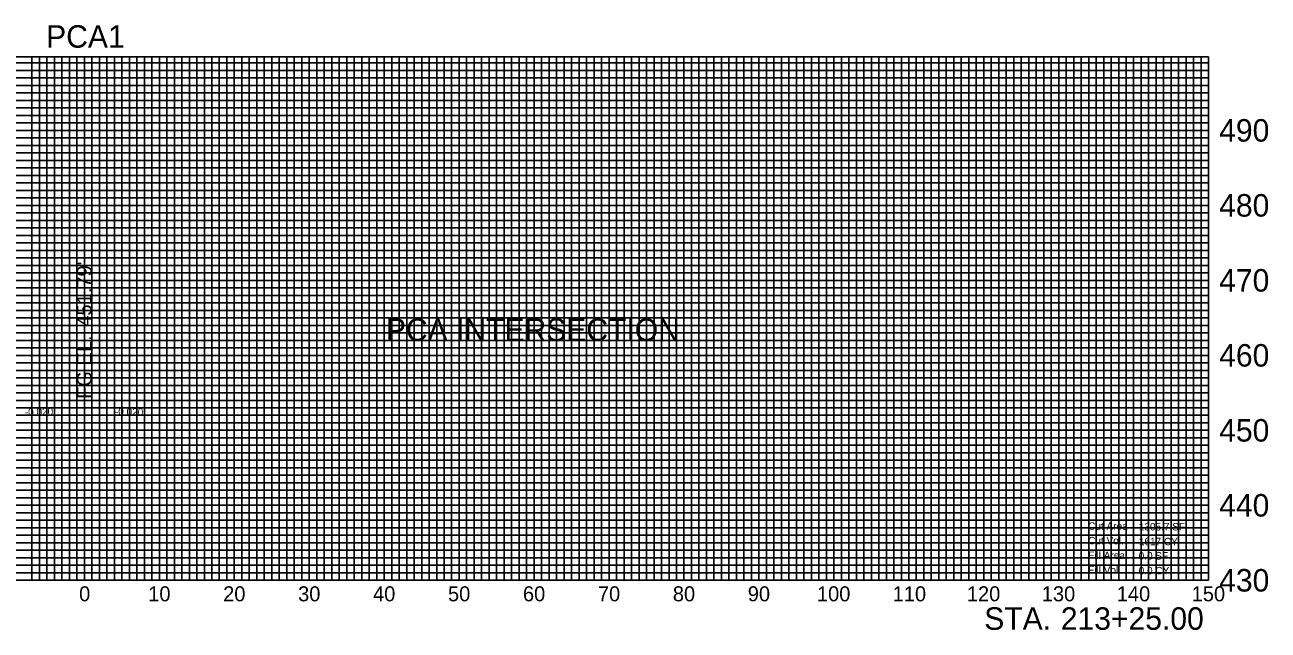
# Model space of a CAD drawing. Extents: x -158 to 158, y 423 to 504.
# Drawn here: x -7.9 to 157.9, y 423.4 to 504.1 of the extents above; entities that cross this region are included whole.
import ezdxf

# ---------------------------------------------------------------- set-up
doc = ezdxf.new("R2010")
doc.units = 0
for name, color, linetype in [('Default', 7, 'Continuous'), ('DES - SHEET - Light Grid', 7, 'Continuous'), ('DES - SHEET - Linework', 7, 'Continuous'), ('DES - XS - Earthwork - Cut Text', 7, 'Continuous'), ('DES - XS - Earthwork - Fill Text', 7, 'Continuous'), ('DES - XS - Proposed - Finished Grade Slopes Text', 7, 'Continuous'), ('DES - XS - Proposed - Text', 7, 'Continuous'), ('Draft_XS_Volume_Annotation', 7, 'Continuous')]:
    doc.layers.add(name, color=color, linetype=linetype)

msp = doc.modelspace()

# ---------------------------------------------------------------- linework, layer by layer
at = {"layer": 'Default'}
msp.add_circle((0, 438.4), 0.012, dxfattribs=at)
msp.add_circle((0, 438.4), 0.012, dxfattribs=at)
msp.add_circle((0, 438.4), 0.012, dxfattribs=at)
at = {"layer": 'DES - SHEET - Light Grid'}
for p, q in [((-7, 430), (-7, 499.82)), ((-7, 430), (-7, 499.82)), ((-6, 430), (-6, 499.82)), ((-6, 430), (-6, 499.82)), ((-5, 430), (-5, 499.82)), ((-5, 430), (-5, 499.82)), ((-4, 430), (-4, 499.82)), ((-4, 430), (-4, 499.82)), ((-3, 430), (-3, 499.82)), ((-3, 430), (-3, 499.82)), ((-2, 430), (-2, 499.82)), ((-2, 430), (-2, 499.82)), ((-1, 430), (-1, 499.82)), ((-1, 430), (-1, 499.82)), ((1, 430), (1, 499.82)), ((1, 430), (1, 499.82)), ((2, 430), (2, 499.82)), ((2, 430), (2, 499.82)), ((3, 430), (3, 499.82)), ((3, 430), (3, 499.82)), ((4, 430), (4, 499.82)), ((4, 430), (4, 499.82)), ((5, 430), (5, 499.82)), ((5, 430), (5, 499.82)), ((6, 430), (6, 499.82)), ((6, 430), (6, 499.82)), ((7, 430), (7, 499.82)), ((7, 430), (7, 499.82)), ((8, 430), (8, 499.82)), ((8, 430), (8, 499.82)), ((9, 430), (9, 499.82)), ((9, 430), (9, 499.82)), ((11, 430), (11, 499.82)), ((11, 430), (11, 499.82)), ((12, 430), (12, 499.82)), ((12, 430), (12, 499.82)), ((13, 430), (13, 499.82)), ((13, 430), (13, 499.82)), ((14, 430), (14, 499.82)), ((14, 430), (14, 499.82)), ((15, 430), (15, 499.82)), ((15, 430), (15, 499.82)), ((16, 430), (16, 499.82)), ((16, 430), (16, 499.82)), ((17, 430), (17, 499.82)), ((17, 430), (17, 499.82)), ((18, 430), (18, 499.82)), ((18, 430), (18, 499.82)), ((19, 430), (19, 499.82)), ((19, 430), (19, 499.82)), ((21, 430), (21, 499.82)), ((21, 430), (21, 499.82)), ((22, 430), (22, 499.82)), ((22, 430), (22, 499.82)), ((23, 430), (23, 499.82)), ((23, 430), (23, 499.82)), ((24, 430), (24, 499.82)), ((24, 430), (24, 499.82)), ((25, 430), (25, 499.82)), ((25, 430), (25, 499.82)), ((26, 430), (26, 499.82)), ((26, 430), (26, 499.82)), ((27, 430), (27, 499.82)), ((27, 430), (27, 499.82)), ((28, 430), (28, 499.82)), ((28, 430), (28, 499.82)), ((29, 430), (29, 499.82)), ((29, 430), (29, 499.82)), ((31, 430), (31, 499.82)), ((31, 430), (31, 499.82)), ((32, 430), (32, 499.82)), ((32, 430), (32, 499.82)), ((33, 430), (33, 499.82)), ((33, 430), (33, 499.82)), ((34, 430), (34, 499.82)), ((34, 430), (34, 499.82)), ((35, 430), (35, 499.82)), ((35, 430), (35, 499.82)), ((36, 430), (36, 499.82)), ((36, 430), (36, 499.82)), ((37, 430), (37, 499.82)), ((37, 430), (37, 499.82)), ((38, 430), (38, 499.82)), ((38, 430), (38, 499.82)), ((39, 430), (39, 499.82)), ((39, 430), (39, 499.82)), ((41, 430), (41, 499.82)), ((41, 430), (41, 499.82)), ((42, 430), (42, 499.82)), ((42, 430), (42, 499.82)), ((43, 430), (43, 499.82)), ((43, 430), (43, 499.82)), ((44, 430), (44, 499.82)), ((44, 430), (44, 499.82)), ((45, 430), (45, 499.82)), ((45, 430), (45, 499.82)), ((46, 430), (46, 499.82)), ((46, 430), (46, 499.82)), ((47, 430), (47, 499.82)), ((47, 430), (47, 499.82)), ((48, 430), (48, 499.82)), ((48, 430), (48, 499.82)), ((49, 430), (49, 499.82)), ((49, 430), (49, 499.82)), ((51, 430), (51, 499.82)), ((51, 430), (51, 499.82)), ((52, 430), (52, 499.82)), ((52, 430), (52, 499.82)), ((53, 430), (53, 499.82)), ((53, 430), (53, 499.82)), ((54, 430), (54, 499.82)), ((54, 430), (54, 499.82)), ((55, 430), (55, 499.82)), ((55, 430), (55, 499.82)), ((56, 430), (56, 499.82)), ((56, 430), (56, 499.82)), ((57, 430), (57, 499.82)), ((57, 430), (57, 499.82)), ((58, 430), (58, 499.82)), ((58, 430), (58, 499.82)), ((59, 430), (59, 499.82)), ((59, 430), (59, 499.82)), ((61, 430), (61, 499.82)), ((61, 430), (61, 499.82)), ((62, 430), (62, 499.82)), ((62, 430), (62, 499.82)), ((63, 430), (63, 499.82)), ((63, 430), (63, 499.82)), ((64, 430), (64, 499.82)), ((64, 430), (64, 499.82)), ((65, 430), (65, 499.82)), ((65, 430), (65, 499.82)), ((66, 430), (66, 499.82)), ((66, 430), (66, 499.82)), ((67, 430), (67, 499.82)), ((67, 430), (67, 499.82)), ((68, 430), (68, 499.82)), ((68, 430), (68, 499.82)), ((69, 430), (69, 499.82)), ((69, 430), (69, 499.82)), ((71, 430), (71, 499.82)), ((71, 430), (71, 499.82)), ((72, 430), (72, 499.82)), ((72, 430), (72, 499.82)), ((73, 430), (73, 499.82)), ((73, 430), (73, 499.82)), ((74, 430), (74, 499.82)), ((74, 430), (74, 499.82)), ((75, 430), (75, 499.82)), ((75, 430), (75, 499.82)), ((76, 430), (76, 499.82)), ((76, 430), (76, 499.82)), ((77, 430), (77, 499.82)), ((77, 430), (77, 499.82)), ((78, 430), (78, 499.82)), ((78, 430), (78, 499.82)), ((79, 430), (79, 499.82)), ((79, 430), (79, 499.82)), ((81, 430), (81, 499.82)), ((81, 430), (81, 499.82)), ((82, 430), (82, 499.82)), ((82, 430), (82, 499.82)), ((83, 430), (83, 499.82)), ((83, 430), (83, 499.82)), ((84, 430), (84, 499.82)), ((84, 430), (84, 499.82)), ((85, 430), (85, 499.82)), ((85, 430), (85, 499.82)), ((86, 430), (86, 499.82)), ((86, 430), (86, 499.82)), ((87, 430), (87, 499.82)), ((87, 430), (87, 499.82)), ((88, 430), (88, 499.82)), ((88, 430), (88, 499.82)), ((89, 430), (89, 499.82)), ((89, 430), (89, 499.82)), ((91, 430), (91, 499.82)), ((91, 430), (91, 499.82)), ((92, 430), (92, 499.82)), ((92, 430), (92, 499.82)), ((93, 430), (93, 499.82)), ((93, 430), (93, 499.82)), ((94, 430), (94, 499.82)), ((94, 430), (94, 499.82)), ((95, 430), (95, 499.82)), ((95, 430), (95, 499.82)), ((96, 430), (96, 499.82)), ((96, 430), (96, 499.82)), ((97, 430), (97, 499.82)), ((97, 430), (97, 499.82)), ((98, 430), (98, 499.82)), ((98, 430), (98, 499.82)), ((99, 430), (99, 499.82)), ((99, 430), (99, 499.82)), ((101, 430), (101, 499.82)), ((101, 430), (101, 499.82)), ((102, 430), (102, 499.82)), ((102, 430), (102, 499.82)), ((103, 430), (103, 499.82)), ((103, 430), (103, 499.82)), ((104, 430), (104, 499.82)), ((104, 430), (104, 499.82)), ((105, 430), (105, 499.82)), ((105, 430), (105, 499.82)), ((106, 430), (106, 499.82)), ((106, 430), (106, 499.82)), ((107, 430), (107, 499.82)), ((107, 430), (107, 499.82)), ((108, 430), (108, 499.82)), ((108, 430), (108, 499.82)), ((109, 430), (109, 499.82)), ((109, 430), (109, 499.82)), ((111, 430), (111, 499.82)), ((111, 430), (111, 499.82)), ((112, 430), (112, 499.82)), ((112, 430), (112, 499.82)), ((113, 430), (113, 499.82)), ((113, 430), (113, 499.82)), ((114, 430), (114, 499.82)), ((114, 430), (114, 499.82)), ((115, 430), (115, 499.82)), ((115, 430), (115, 499.82)), ((116, 430), (116, 499.82)), ((116, 430), (116, 499.82)), ((117, 430), (117, 499.82)), ((117, 430), (117, 499.82)), ((118, 430), (118, 499.82)), ((118, 430), (118, 499.82)), ((119, 430), (119, 499.82)), ((119, 430), (119, 499.82)), ((121, 430), (121, 499.82)), ((121, 430), (121, 499.82)), ((122, 430), (122, 499.82)), ((122, 430), (122, 499.82)), ((123, 430), (123, 499.82)), ((123, 430), (123, 499.82)), ((124, 430), (124, 499.82)), ((124, 430), (124, 499.82)), ((125, 430), (125, 499.82)), ((125, 430), (125, 499.82)), ((126, 430), (126, 499.82)), ((126, 430), (126, 499.82)), ((127, 430), (127, 499.82)), ((127, 430), (127, 499.82)), ((128, 430), (128, 499.82)), ((128, 430), (128, 499.82)), ((129, 430), (129, 499.82)), ((129, 430), (129, 499.82)), ((131, 430), (131, 499.82)), ((131, 430), (131, 499.82)), ((132, 430), (132, 499.82)), ((132, 430), (132, 499.82)), ((133, 430), (133, 499.82)), ((133, 430), (133, 499.82)), ((134, 430), (134, 499.82)), ((134, 430), (134, 499.82)), ((135, 430), (135, 499.82)), ((135, 430), (135, 499.82)), ((136, 430), (136, 499.82)), ((136, 430), (136, 499.82)), ((137, 430), (137, 499.82)), ((137, 430), (137, 499.82)), ((138, 430), (138, 499.82)), ((138, 430), (138, 499.82)), ((139, 430), (139, 499.82)), ((139, 430), (139, 499.82)), ((141, 430), (141, 499.82)), ((141, 430), (141, 499.82)), ((142, 430), (142, 499.82)), ((142, 430), (142, 499.82)), ((143, 430), (143, 499.82)), ((143, 430), (143, 499.82)), ((144, 430), (144, 499.82)), ((144, 430), (144, 499.82)), ((145, 430), (145, 499.82)), ((145, 430), (145, 499.82)), ((146, 430), (146, 499.82)), ((146, 430), (146, 499.82)), ((147, 430), (147, 499.82)), ((147, 430), (147, 499.82)), ((148, 430), (148, 499.82)), ((148, 430), (148, 499.82)), ((149, 430), (149, 499.82)), ((149, 430), (149, 499.82)), ((-150, 499), (150, 499)), ((-150, 499), (150, 499)), ((-150, 498), (150, 498)), ((-150, 498), (150, 498)), ((-150, 497), (150, 497)), ((-150, 497), (150, 497)), ((-150, 496), (150, 496)), ((-150, 496), (150, 496)), ((-150, 495), (150, 495)), ((-150, 495), (150, 495)), ((-150, 494), (150, 494)), ((-150, 494), (150, 494)), ((-150, 493), (150, 493)), ((-150, 493), (150, 493)), ((-150, 492), (150, 492)), ((-150, 492), (150, 492)), ((-150, 491), (150, 491)), ((-150, 491), (150, 491)), ((-150, 489), (150, 489)), ((-150, 489), (150, 489)), ((-150, 488), (150, 488)), ((-150, 488), (150, 488)), ((-150, 487), (150, 487)), ((-150, 487), (150, 487)), ((-150, 486), (150, 486)), ((-150, 486), (150, 486)), ((-150, 485), (150, 485)), ((-150, 485), (150, 485)), ((-150, 484), (150, 484)), ((-150, 484), (150, 484)), ((-150, 483), (150, 483)), ((-150, 483), (150, 483)), ((-150, 482), (150, 482)), ((-150, 482), (150, 482)), ((-150, 481), (150, 481)), ((-150, 481), (150, 481)), ((-150, 479), (150, 479)), ((-150, 479), (150, 479)), ((-150, 478), (150, 478)), ((-150, 478), (150, 478)), ((-150, 477), (150, 477)), ((-150, 477), (150, 477)), ((-150, 476), (150, 476)), ((-150, 476), (150, 476)), ((-150, 475), (150, 475)), ((-150, 475), (150, 475)), ((-150, 474), (150, 474)), ((-150, 474), (150, 474)), ((-150, 473), (150, 473)), ((-150, 473), (150, 473)), ((-150, 472), (150, 472)), ((-150, 472), (150, 472)), ((-150, 471), (150, 471)), ((-150, 471), (150, 471)), ((-150, 469), (150, 469)), ((-150, 469), (150, 469)), ((-150, 468), (150, 468)), ((-150, 468), (150, 468)), ((-150, 467), (150, 467)), ((-150, 467), (150, 467)), ((-150, 466), (150, 466)), ((-150, 466), (150, 466)), ((-150, 465), (150, 465)), ((-150, 465), (150, 465)), ((-150, 464), (150, 464)), ((-150, 464), (150, 464)), ((-150, 463), (150, 463)), ((-150, 463), (150, 463)), ((-150, 462), (150, 462)), ((-150, 462), (150, 462)), ((-150, 461), (150, 461)), ((-150, 461), (150, 461)), ((-150, 459), (150, 459)), ((-150, 459), (150, 459)), ((-150, 458), (150, 458)), ((-150, 458), (150, 458)), ((-150, 457), (150, 457)), ((-150, 457), (150, 457)), ((-150, 456), (150, 456)), ((-150, 456), (150, 456)), ((-150, 455), (150, 455)), ((-150, 455), (150, 455)), ((-150, 454), (150, 454)), ((-150, 454), (150, 454)), ((-150, 453), (150, 453)), ((-150, 453), (150, 453)), ((-150, 452), (150, 452)), ((-150, 452), (150, 452)), ((-150, 451), (150, 451)), ((-150, 451), (150, 451)), ((-150, 449), (150, 449)), ((-150, 449), (150, 449)), ((-150, 448), (150, 448)), ((-150, 448), (150, 448)), ((-150, 447), (150, 447)), ((-150, 447), (150, 447)), ((-150, 446), (150, 446)), ((-150, 446), (150, 446)), ((-150, 445), (150, 445)), ((-150, 445), (150, 445)), ((-150, 444), (150, 444)), ((-150, 444), (150, 444)), ((-150, 443), (150, 443)), ((-150, 443), (150, 443)), ((-150, 442), (150, 442)), ((-150, 442), (150, 442)), ((-150, 441), (150, 441)), ((-150, 441), (150, 441)), ((-150, 439), (150, 439)), ((-150, 439), (150, 439)), ((-150, 438), (150, 438)), ((-150, 438), (150, 438)), ((-150, 437), (150, 437)), ((-150, 437), (150, 437)), ((-150, 436), (150, 436)), ((-150, 436), (150, 436)), ((-150, 435), (150, 435)), ((-150, 435), (150, 435)), ((-150, 434), (150, 434)), ((-150, 434), (150, 434)), ((-150, 433), (150, 433)), ((-150, 433), (150, 433)), ((-150, 432), (150, 432)), ((-150, 432), (150, 432)), ((-150, 431), (150, 431)), ((-150, 431), (150, 431))]:
    msp.add_line(p, q, dxfattribs=at)
at = {"layer": 'DES - SHEET - Linework'}
for p, q in [((-150, 499.82), (150, 499.82)), ((-150, 499.82), (150, 499.82)), ((0, 430), (0, 499.82)), ((0, 430), (0, 499.82)), ((10, 430), (10, 499.82)), ((10, 430), (10, 499.82)), ((20, 430), (20, 499.82)), ((20, 430), (20, 499.82)), ((30, 430), (30, 499.82)), ((30, 430), (30, 499.82)), ((40, 430), (40, 499.82)), ((40, 430), (40, 499.82)), ((50, 430), (50, 499.82)), ((50, 430), (50, 499.82)), ((60, 430), (60, 499.82)), ((60, 430), (60, 499.82)), ((70, 430), (70, 499.82)), ((70, 430), (70, 499.82)), ((80, 430), (80, 499.82)), ((80, 430), (80, 499.82)), ((90, 430), (90, 499.82)), ((90, 430), (90, 499.82)), ((100, 430), (100, 499.82)), ((100, 430), (100, 499.82)), ((110, 430), (110, 499.82)), ((110, 430), (110, 499.82)), ((120, 430), (120, 499.82)), ((120, 430), (120, 499.82)), ((130, 430), (130, 499.82)), ((130, 430), (130, 499.82)), ((140, 430), (140, 499.82)), ((140, 430), (140, 499.82)), ((150, 430), (150, 499.82)), ((150, 430), (150, 499.82)), ((-150, 490), (150, 490)), ((-150, 490), (150, 490)), ((-150, 480), (150, 480)), ((-150, 480), (150, 480)), ((-150, 470), (150, 470)), ((-150, 470), (150, 470)), ((-150, 460), (150, 460)), ((-150, 460), (150, 460)), ((-150, 450), (150, 450)), ((-150, 450), (150, 450)), ((-150, 440), (150, 440)), ((-150, 440), (150, 440)), ((-150, 430), (150, 430)), ((-150, 430), (150, 430))]:
    msp.add_line(p, q, dxfattribs=at)
at = {"layer": 'Draft_XS_Volume_Annotation'}
msp.add_circle((0, 438.4), 0.012, dxfattribs=at)
msp.add_circle((0, 438.4), 0.012, dxfattribs=at)
msp.add_circle((0, 438.4), 0.012, dxfattribs=at)
msp.add_circle((0, 438.4), 0.012, dxfattribs=at)
msp.add_circle((0, 438.4), 0.012, dxfattribs=at)
msp.add_circle((0, 438.4), 0.012, dxfattribs=at)

# ---------------------------------------------------------------- texts
at = {"layer": 'DES - XS - Earthwork - Cut Text'}
for s, p in [('Cut Area', (133.93, 436.74)), ('1305.7 SF', (140.69, 436.65)), ('Cut Vol.', (133.93, 434.79)), ('1617 CY', (140.69, 434.67))]:
    msp.add_text(s, height=1, dxfattribs=at).set_placement(p)
at = {"layer": 'DES - XS - Earthwork - Fill Text'}
for s, p in [('Fill Area', (133.93, 432.83)), ('0.0 SF', (140.67, 432.76)), ('Fill Vol.', (133.93, 430.88)), ('0.0 CY', (140.67, 430.79))]:
    msp.add_text(s, height=1, dxfattribs=at).set_placement(p)
at = {"layer": 'DES - XS - Proposed - Finished Grade Slopes Text'}
for rotation, p in [(1.1458, (-7.95, 451.93)), (1.1458, (-7.95, 451.93)), (358.8542, (4.05, 452.01)), (358.8542, (4.05, 452.01))]:
    msp.add_text('-0.020', height=1, rotation=rotation, dxfattribs=at).set_placement(p)
at = {"layer": 'DES - XS - Proposed - Text'}
for s, height, p in [('PCA1', 3, (-5.11, 501.02)), ('PCA1', 3, (-5.11, 501.02)), ('490', 3, (151.41, 488.5)), ('490', 3, (151.41, 488.5)), ('480', 3, (151.41, 478.5)), ('480', 3, (151.41, 478.5)), ('470', 3, (151.41, 468.5)), ('470', 3, (151.41, 468.5)), ('PCA INTERSECTION', 3, (40.22, 461.91)), ('460', 3, (151.41, 458.5)), ('460', 3, (151.41, 458.5)), ('450', 3, (151.41, 448.5)), ('450', 3, (151.41, 448.5)), ('440', 3, (151.41, 438.5)), ('440', 3, (151.41, 438.5)), ('430', 3, (151.41, 428.5)), ('430', 3, (151.41, 428.5)), ('0', 2, (-0.71, 427.2)), ('0', 2, (-0.71, 427.2)), ('10', 2, (8.51, 427.2)), ('10', 2, (8.51, 427.2)), ('20', 2, (18.51, 427.2)), ('20', 2, (18.51, 427.2)), ('30', 2, (28.51, 427.2)), ('30', 2, (28.51, 427.2)), ('40', 2, (38.51, 427.2)), ('40', 2, (38.51, 427.2)), ('50', 2, (48.51, 427.2)), ('50', 2, (48.51, 427.2)), ('60', 2, (58.51, 427.2)), ('60', 2, (58.51, 427.2)), ('70', 2, (68.51, 427.2)), ('70', 2, (68.51, 427.2)), ('80', 2, (78.51, 427.2)), ('80', 2, (78.51, 427.2)), ('90', 2, (88.51, 427.2)), ('90', 2, (88.51, 427.2)), ('100', 2, (97.74, 427.2)), ('100', 2, (97.74, 427.2)), ('110', 2, (107.84, 427.2)), ('110', 2, (107.84, 427.2)), ('120', 2, (117.74, 427.2)), ('120', 2, (117.74, 427.2)), ('130', 2, (127.74, 427.2)), ('130', 2, (127.74, 427.2)), ('140', 2, (137.74, 427.2)), ('140', 2, (137.74, 427.2)), ('150', 2, (147.74, 427.2)), ('150', 2, (147.74, 427.2)), (' STA. ', 3, (118.95, 423.4)), (' STA. ', 3, (118.95, 423.4)), ('213+25.00', 3, (130.28, 423.4)), ('213+25.00', 3, (130.28, 423.4))]:
    msp.add_text(s, height=height, dxfattribs=at).set_placement(p)
for s, p in [("451.79'", (0.98, 463.82)), ("451.79'", (0.98, 463.82)), ('FG EL. ', (0.98, 454.19)), ('FG EL. ', (0.98, 454.19))]:
    msp.add_text(s, height=2, rotation=90, dxfattribs=at).set_placement(p)

doc.saveas('drawing.dxf')
